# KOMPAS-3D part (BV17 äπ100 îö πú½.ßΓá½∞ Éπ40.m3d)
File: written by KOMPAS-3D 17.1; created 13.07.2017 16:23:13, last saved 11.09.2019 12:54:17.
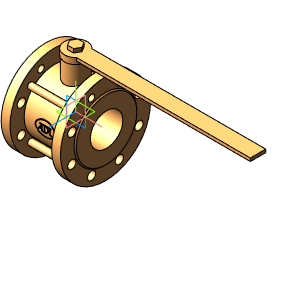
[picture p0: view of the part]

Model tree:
1. Операция без истории:2  (labels: Сталь 20  ГОСТ 1050-88)

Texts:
  DISO1
  DISO2
  BV17 Ду10 ФФ Ру40 угл. сталь
  BV17 Ду15 ФФ Ру40 угл. сталь
  BV17 Ду20 ФФ Ру40 угл. сталь
  BV17 Ду25 ФФ Ру40 угл. сталь
  BV17 Ду32 ФФ Ру40 угл. сталь
  BV17 Ду40 ФФ Ру40 угл. сталь
  BV17 Ду50 ФФ Ру40 угл. сталь
  BV17 Ду65 ФФ Ру40 угл. сталь
  BV17 Ду80 ФФ Ру40 угл. сталь
  BV17 Ду100 ФФ Ру40 угл. сталь
  BV17 Ду125 ФФ Ру40 угл. сталь
  BV17 Ду150 ФФ Ру40 угл. сталь
  BV17 Ду200 ФФ Ру40 угл. сталь
  BV17 Ду250 ФФ Ру40 угл. сталь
